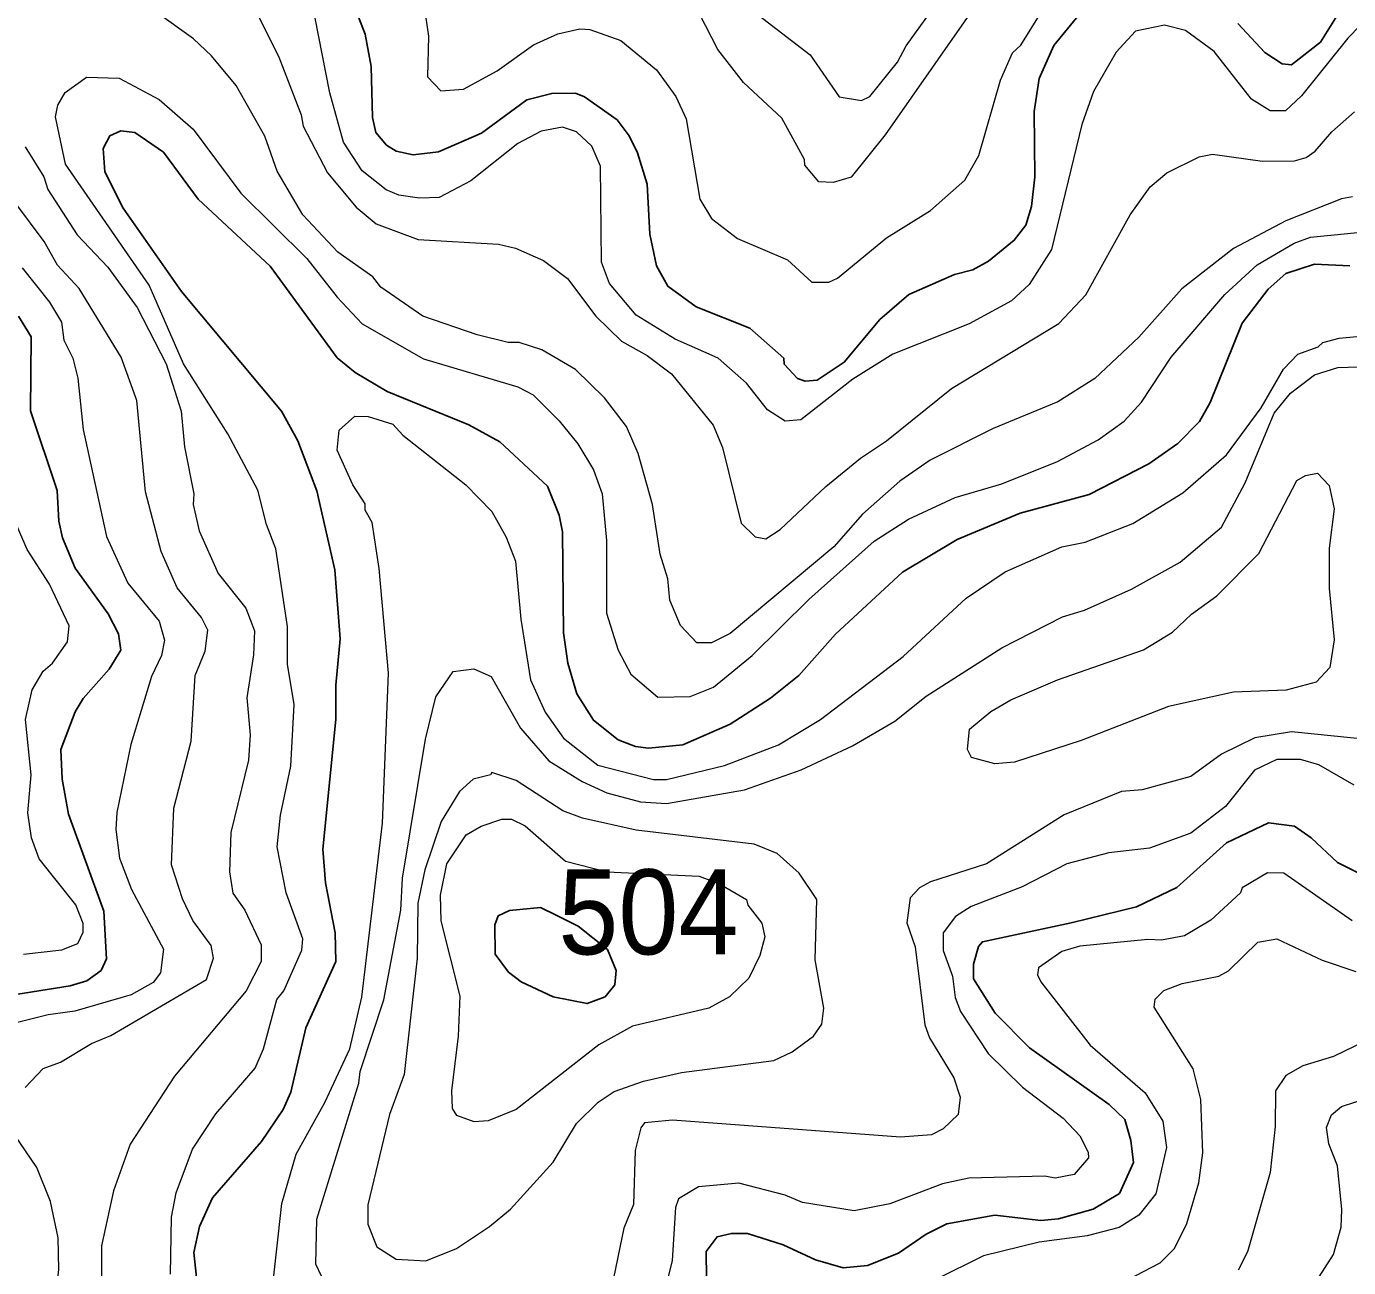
# Model space of a CAD drawing. Extents: x 673.3 to 698.5, y 6984.3 to 7012.3.
# Drawn here: x 691.793 to 693.038, y 6987.584 to 6988.753 of the extents above; entities that cross this region are included whole.
import ezdxf

# ---------------------------------------------------------------- set-up
doc = ezdxf.new("R2010")
doc.units = 0
doc.header["$LTSCALE"] = 0.032
doc.layers.add('1', color=7, linetype='Continuous', lineweight=25)
doc.layers.add('2', color=7, linetype='Continuous', lineweight=13)
doc.layers.add('21', color=7, linetype='Continuous')

msp = doc.modelspace()

# ---------------------------------------------------------------- linework, layer by layer
at = {"layer": '1'}
for points in [[(692.9334, 6988.7559), (692.9587, 6988.7284), (692.9751, 6988.7177), (692.9838, 6988.7167), (693.0111, 6988.7381), (693.0283, 6988.7658)], [(692.1053, 6988.7626), (692.112, 6988.7457), (692.1176, 6988.7153), (692.1188, 6988.6672), (692.1218, 6988.6532), (692.132, 6988.6412), (692.141, 6988.6354), (692.1572, 6988.632), (692.181, 6988.635), (692.2213, 6988.6525), (692.2641, 6988.6838), (692.2875, 6988.6899), (692.3099, 6988.69), (692.3183, 6988.6868), (692.349, 6988.6651), (692.3603, 6988.6499), (692.3683, 6988.6339), (692.3774, 6988.6043), (692.3798, 6988.5573), (692.386, 6988.5274), (692.3969, 6988.5084), (692.4236, 6988.4888), (692.4741, 6988.4687), (692.5059, 6988.4406), (692.5063, 6988.4348), (692.5189, 6988.4213), (692.5261, 6988.419), (692.5373, 6988.42), (692.5629, 6988.4368), (692.5962, 6988.477), (692.6235, 6988.5004), (692.6667, 6988.5194), (692.6839, 6988.5238), (692.6985, 6988.532), (692.7229, 6988.5516), (692.7339, 6988.5657), (692.7391, 6988.5834), (692.7422, 6988.6112), (692.7415, 6988.673), (692.7464, 6988.7039), (692.7603, 6988.7349), (692.7843, 6988.7645)], [(692.0142, 6987.7031), (692.0347, 6987.7332), (692.0419, 6987.7495), (692.056, 6987.8101), (692.0842, 6987.8725), (692.0836, 6987.8994), (692.0744, 6987.9465), (692.0721, 6987.9781), (692.0842, 6988.1003), (692.0843, 6988.1326), (692.0883, 6988.1763), (692.0834, 6988.2414), (692.0664, 6988.3157), (692.0486, 6988.3628), (692.0331, 6988.3907), (691.9389, 6988.5035), (691.8839, 6988.5819), (691.8668, 6988.616), (691.8652, 6988.6381), (691.8715, 6988.6501), (691.882, 6988.6546), (691.895, 6988.6531), (691.9219, 6988.6346), (691.9547, 6988.5904), (692.0224, 6988.5271), (692.0856, 6988.4408), (692.1023, 6988.4272), (692.1325, 6988.4091), (692.2096, 6988.3779), (692.2387, 6988.3618), (692.2835, 6988.3202), (692.2944, 6988.2929), (692.2976, 6988.2772), (692.2986, 6988.182), (692.3027, 6988.1535), (692.3112, 6988.1245), (692.3268, 6988.0996), (692.35, 6988.0813), (692.3663, 6988.0749), (692.3786, 6988.0735), (692.4109, 6988.0764), (692.4556, 6988.0961), (692.4935, 6988.1205), (692.52, 6988.1418), (692.5547, 6988.1806), (692.6177, 6988.2391), (692.6692, 6988.2698), (692.7286, 6988.2946), (692.7933, 6988.3122), (692.8495, 6988.3411), (692.8769, 6988.3604), (692.8972, 6988.381), (692.9074, 6988.3988), (692.9376, 6988.4737), (692.9619, 6988.5055), (692.9787, 6988.5202), (693.0055, 6988.5292), (693.0387, 6988.5277)], [(691.7119, 6987.83), (691.8341, 6987.8495), (691.8497, 6987.8543), (691.8635, 6987.8641), (691.8684, 6987.875), (691.866, 6987.9199), (691.8327, 6988.0112), (691.8265, 6988.0442), (691.8253, 6988.0721), (691.8388, 6988.1077), (691.8465, 6988.12), (691.871, 6988.1477), (691.8818, 6988.1655), (691.8798, 6988.1809), (691.8699, 6988.1998), (691.839, 6988.243), (691.8271, 6988.2714), (691.8236, 6988.287), (691.822, 6988.316), (691.7968, 6988.3909), (691.7975, 6988.4606), (691.7855, 6988.4803)], [(693.0717, 6987.9435), (693.0273, 6987.9658), (693.0025, 6987.989), (692.9868, 6987.9998), (692.9621, 6988.0032), (692.9228, 6987.9841), (692.876, 6987.9423), (692.8379, 6987.9239), (692.7764, 6987.9088), (692.693, 6987.8911), (692.6892, 6987.8865)], [(692.6892, 6987.8865), (692.6845, 6987.87), (692.6845, 6987.8562), (692.705, 6987.8237), (692.7371, 6987.7911), (692.8122, 6987.7378), (692.8269, 6987.7237), (692.8326, 6987.7039), (692.8351, 6987.6832), (692.822, 6987.6541), (692.7973, 6987.6392), (692.7647, 6987.6303), (692.748, 6987.6287), (692.7045, 6987.6335), (692.6593, 6987.6255), (692.6401, 6987.6158), (692.614, 6987.5979), (692.5847, 6987.5862), (692.5617, 6987.5839), (692.5358, 6987.5917), (692.5055, 6987.6056), (692.4719, 6987.6164), (692.4567, 6987.6164), (692.4431, 6987.6133), (692.4328, 6987.5994), (692.4336, 6987.5485)], [(691.9531, 6987.5749), (691.9505, 6987.5983), (691.9558, 6987.6228), (691.9683, 6987.6498), (692.0142, 6987.7031)]]:
    msp.add_lwpolyline(points, dxfattribs=at)
msp.add_lwpolyline([(692.2588, 6987.8533), (692.2468, 6987.8624), (692.2341, 6987.8795), (692.234, 6987.9069), (692.2371, 6987.9156), (692.2477, 6987.9205), (692.2769, 6987.9234), (692.2916, 6987.9162), (692.3123, 6987.9059), (692.3399, 6987.8837), (692.3482, 6987.864), (692.347, 6987.8504), (692.3377, 6987.8392), (692.3207, 6987.8328), (692.2887, 6987.8392)], close=True, dxfattribs=at)
at = {"layer": '2'}
for points in [[(692.4821, 6988.7635), (692.5307, 6988.7262), (692.5582, 6988.6866), (692.5791, 6988.6833), (692.587, 6988.6869), (692.6131, 6988.7194), (692.6212, 6988.7347), (692.6706, 6988.8038)], [(692.1633, 6988.7995), (692.1714, 6988.7437), (692.1706, 6988.7055), (692.1831, 6988.6923), (692.2045, 6988.6938), (692.236, 6988.7111), (692.2702, 6988.7356), (692.2933, 6988.7461), (692.3139, 6988.7508), (692.3233, 6988.7501), (692.3525, 6988.7397), (692.386, 6988.712), (692.4044, 6988.6871), (692.4141, 6988.6659), (692.4269, 6988.5902), (692.4379, 6988.5722), (692.4623, 6988.5533), (692.5095, 6988.5332), (692.5322, 6988.5123), (692.5482, 6988.5121), (692.5566, 6988.5158), (692.6025, 6988.5539), (692.6439, 6988.5795), (692.6764, 6988.6083), (692.6897, 6988.6314), (692.7101, 6988.7025), (692.7213, 6988.7281), (692.7292, 6988.7354), (692.7481, 6988.7662)], [(692.7004, 6988.7931), (692.6015, 6988.6509), (692.5695, 6988.611), (692.5523, 6988.606), (692.5389, 6988.6067), (692.5259, 6988.6224), (692.5254, 6988.6277), (692.504, 6988.6667), (692.468, 6988.7002), (692.4439, 6988.7313), (692.4151, 6988.7878)], [(693.0726, 6988.7791), (693.0368, 6988.7418), (692.9932, 6988.6876), (692.9783, 6988.6736), (692.9638, 6988.6736), (692.9463, 6988.6845), (692.911, 6988.7295), (692.8842, 6988.7491), (692.8642, 6988.7541), (692.837, 6988.7485), (692.8187, 6988.7286), (692.7974, 6988.6916), (692.7864, 6988.6606), (692.7579, 6988.543), (692.7369, 6988.5101), (692.7204, 6988.4945), (692.6805, 6988.4728), (692.6085, 6988.4445), (692.571, 6988.4208), (692.522, 6988.3826), (692.5071, 6988.3812), (692.4905, 6988.3919), (692.4708, 6988.4172), (692.4441, 6988.4405), (692.4037, 6988.4584), (692.3671, 6988.4812), (692.3419, 6988.5109), (692.3343, 6988.531), (692.3333, 6988.6215), (692.3252, 6988.6401), (692.3109, 6988.6538), (692.2976, 6988.658), (692.2775, 6988.6545), (692.2555, 6988.6427), (692.2113, 6988.6075), (692.1816, 6988.592), (692.163, 6988.5913), (692.1436, 6988.594), (692.1315, 6988.599), (692.1089, 6988.6171), (692.0914, 6988.644), (692.0785, 6988.6906), (692.0646, 6988.7623)], [(693.0413, 6988.5924), (693.0308, 6988.5905), (692.9784, 6988.57), (692.9293, 6988.5439), (692.8807, 6988.5058), (692.8403, 6988.4604), (692.7989, 6988.4214), (692.764, 6988.3994), (692.7029, 6988.3745), (692.6438, 6988.3445), (692.6153, 6988.3249), (692.5799, 6988.2938), (692.5531, 6988.2628), (692.4555, 6988.1813), (692.4378, 6988.1727), (692.4241, 6988.1727), (692.4088, 6988.1888), (692.3987, 6988.2128), (692.3969, 6988.2329), (692.3896, 6988.2561), (692.3822, 6988.3029), (692.3688, 6988.3508), (692.3578, 6988.3762), (692.3372, 6988.4034), (692.3098, 6988.43), (692.2783, 6988.4486), (692.2569, 6988.4552), (692.2465, 6988.4554), (692.2172, 6988.4627), (692.166, 6988.4803), (692.1266, 6988.5074), (692.119, 6988.5173), (692.0862, 6988.5403), (692.0532, 6988.5756), (692.0291, 6988.6168), (692.0175, 6988.6497), (691.9904, 6988.6973), (691.9673, 6988.7252), (691.9504, 6988.7412), (691.9138, 6988.7673)], [(692.0097, 6988.7662), (692.0303, 6988.7251), (692.0515, 6988.6697), (692.0535, 6988.6591), (692.0764, 6988.6152), (692.1033, 6988.5828), (692.1222, 6988.5671), (692.1618, 6988.5523), (692.2373, 6988.548), (692.2534, 6988.5441)], [(692.0084, 6987.7721), (692.0162, 6987.7901), (692.0287, 6987.8366), (692.0353, 6987.8447), (692.0524, 6987.883), (692.0532, 6987.8938), (692.0376, 6987.9371), (692.0289, 6987.9804), (692.0321, 6988.0104), (692.0418, 6988.0564), (692.045, 6988.1146), (692.0387, 6988.1525), (692.0386, 6988.1879), (692.0279, 6988.2611), (692.0189, 6988.284), (692.0108, 6988.3163), (691.9826, 6988.3695), (691.9407, 6988.4352), (691.9085, 6988.5095), (691.8297, 6988.6232), (691.8204, 6988.6677), (691.8227, 6988.6788), (691.8295, 6988.6908), (691.8495, 6988.7051), (691.8804, 6988.7044), (691.9179, 6988.6842), (691.95, 6988.6562), (691.9948, 6988.5959), (692.057, 6988.5345), (692.0854, 6988.4982), (692.1089, 6988.473), (692.1668, 6988.44), (692.2555, 6988.4136), (692.2699, 6988.4062), (692.2945, 6988.3817), (692.3122, 6988.3599), (692.3269, 6988.3355), (692.335, 6988.3128), (692.3391, 6988.269), (692.3391, 6988.2006), (692.35, 6988.1655), (692.3621, 6988.1431), (692.3875, 6988.1213), (692.4179, 6988.1221), (692.4399, 6988.1307), (692.4761, 6988.1606), (692.5296, 6988.2133), (692.5911, 6988.2683), (692.6233, 6988.2891), (692.6673, 6988.3094), (692.7111, 6988.3224), (692.7635, 6988.3432), (692.802, 6988.3637), (692.8263, 6988.3813)], [(692.2534, 6988.5441), (692.2797, 6988.5326), (692.3023, 6988.5157), (692.329, 6988.4802), (692.3531, 6988.4567), (692.3772, 6988.4432), (692.4002, 6988.4259), (692.4395, 6988.3774), (692.4483, 6988.3565), (692.4657, 6988.2851), (692.479, 6988.2723), (692.4891, 6988.2705), (692.5026, 6988.2792), (692.5456, 6988.3197), (692.5782, 6988.3465), (692.6025, 6988.3628), (692.6638, 6988.4119), (692.765, 6988.4731), (692.7903, 6988.5001), (692.832, 6988.5757), (692.8507, 6988.6019), (692.8666, 6988.6152), (692.897, 6988.6303), (692.9095, 6988.6327), (692.9566, 6988.626), (692.9868, 6988.6263), (692.9976, 6988.6295), (693.0063, 6988.6356), (693.022, 6988.6536), (693.0433, 6988.6726)], [(691.7917, 6988.6397), (691.8094, 6988.6114), (691.8131, 6988.5995), (691.8409, 6988.5568), (691.8697, 6988.5264), (691.8971, 6988.4884), (691.9244, 6988.4352), (691.9385, 6988.3906), (691.9419, 6988.3572), (691.9506, 6988.3127), (691.9499, 6988.3027), (691.9556, 6988.278), (691.9734, 6988.2378), (691.9996, 6988.2051), (692.0076, 6988.184), (692.0068, 6988.1613), (692.0004, 6988.1207), (692.0035, 6988.0858), (692.0019, 6988.062), (691.9854, 6987.9941), (691.984, 6987.957), (691.9874, 6987.9368), (691.9987, 6987.9209), (692.0141, 6987.8881), (692.0141, 6987.8725), (691.9999, 6987.8448), (691.9323, 6987.7644), (691.8905, 6987.7006), (691.875, 6987.6566), (691.8636, 6987.6048), (691.8636, 6987.5716)], [(691.7917, 6987.7539), (691.8087, 6987.7717), (691.825, 6987.7776), (691.8543, 6987.7954), (691.8723, 6987.8028), (691.9624, 6987.8556), (691.9692, 6987.8756), (691.9669, 6987.8876), (691.9495, 6987.911), (691.9399, 6987.9315), (691.9296, 6987.9636), (691.9317, 6988.0168), (691.9482, 6988.0798), (691.9519, 6988.1418), (691.9613, 6988.1648), (691.9636, 6988.1845), (691.9578, 6988.1963), (691.9348, 6988.2243), (691.9199, 6988.2584), (691.905, 6988.3146), (691.8969, 6988.4007), (691.8821, 6988.4417), (691.8425, 6988.5063), (691.8222, 6988.5283), (691.8098, 6988.5505), (691.7831, 6988.5862)], [(692.8263, 6988.3813), (692.8426, 6988.3993), (692.8705, 6988.4417), (692.9212, 6988.5006), (692.9517, 6988.5285), (692.9865, 6988.5488), (693.0019, 6988.5545), (693.0745, 6988.5619)], [(691.789, 6988.5258), (691.8148, 6988.4933), (691.826, 6988.4744), (691.8281, 6988.4576), (691.8366, 6988.4406), (691.8415, 6988.4218), (691.8464, 6988.3733), (691.8683, 6988.2726), (691.8885, 6988.2288), (691.9178, 6988.1931), (691.923, 6988.1752), (691.92, 6988.1605), (691.9107, 6988.141), (691.8913, 6988.0768), (691.8781, 6988.0128), (691.8773, 6987.9968), (691.8805, 6987.9697), (691.8918, 6987.9403), (691.9221, 6987.8841), (691.9193, 6987.8618), (691.9122, 6987.8526), (691.8916, 6987.841), (691.8386, 6987.8258), (691.8136, 6987.8224), (691.7543, 6987.8074)], [(692.8816, 6988.3137), (692.9226, 6988.3497), (692.9554, 6988.3939), (692.9764, 6988.4303), (692.99, 6988.4445), (693.009, 6988.4512), (693.0135, 6988.4552), (693.0288, 6988.4593), (693.0621, 6988.4626)], [(692.0709, 6987.5761), (692.0655, 6987.5875), (692.0663, 6987.6297), (692.106, 6987.7579), (692.1071, 6987.769), (692.1293, 6987.8365), (692.1453, 6987.9208), (692.1469, 6987.9509), (692.1688, 6988.0819), (692.1784, 6988.1216), (692.1946, 6988.1455), (692.2142, 6988.1482), (692.2306, 6988.1409), (692.258, 6988.0923), (692.2849, 6988.0615), (692.3161, 6988.0421), (692.3394, 6988.0312), (692.3712, 6988.0228), (692.3955, 6988.0213), (692.4691, 6988.034), (692.5223, 6988.0528), (692.5707, 6988.0754), (692.6106, 6988.0987), (692.6399, 6988.1223), (692.7113, 6988.1678), (692.7683, 6988.197), (692.7889, 6988.2033), (692.8332, 6988.223), (692.879, 6988.2485), (692.9179, 6988.2814), (692.9404, 6988.3231), (692.9675, 6988.3888), (692.9829, 6988.4077), (693.0055, 6988.4248), (693.0276, 6988.4317), (693.0471, 6988.4324)], [(692.1086, 6987.8388), (692.1281, 6988.0027), (692.1338, 6988.1439), (692.125, 6988.2425), (692.1183, 6988.2858), (692.112, 6988.2975), (692.1119, 6988.3035), (692.1004, 6988.3212), (692.0854, 6988.354), (692.0875, 6988.3729), (692.1022, 6988.386), (692.1146, 6988.3858), (692.138, 6988.3784), (692.1472, 6988.368), (692.2067, 6988.3213), (692.231, 6988.2962), (692.2446, 6988.2721), (692.2535, 6988.2495), (692.2585, 6988.1948), (692.2676, 6988.1378), (692.2814, 6988.1073), (692.2987, 6988.0827), (692.331, 6988.0572), (692.3833, 6988.044), (692.3956, 6988.044), (692.4501, 6988.0569), (692.501, 6988.0764), (692.5406, 6988.1003), (692.6184, 6988.1597), (692.6776, 6988.2146), (692.7143, 6988.2393), (692.7677, 6988.2628), (692.7898, 6988.2672), (692.8345, 6988.2848), (692.8816, 6988.3137)], [(691.7901, 6987.8794), (691.8264, 6987.8835), (691.8414, 6987.8894), (691.8464, 6987.9001), (691.8463, 6987.9081), (691.8396, 6987.9257), (691.805, 6987.9691), (691.7978, 6987.989), (691.7943, 6988.0124), (691.7975, 6988.0483), (691.792, 6988.1005), (691.7983, 6988.1284), (691.8086, 6988.146), (691.8175, 6988.1535), (691.8317, 6988.1735), (691.8333, 6988.1886), (691.8148, 6988.2278), (691.7936, 6988.2604), (691.7739, 6988.3062)], [(693.0797, 6988.0791), (692.9839, 6988.0887), (692.9494, 6988.0831), (692.9181, 6988.0676), (692.8891, 6988.0466), (692.8432, 6988.0342), (692.8237, 6988.0325), (692.7699, 6988.0106), (692.6969, 6987.9643), (692.6439, 6987.9474), (692.6337, 6987.9417), (692.625, 6987.9325), (692.6218, 6987.9089), (692.6297, 6987.8863), (692.6388, 6987.8127), (692.6432, 6987.8007), (692.666, 6987.7628), (692.6721, 6987.7446), (692.6701, 6987.7284), (692.6559, 6987.715), (692.645, 6987.7093), (692.6158, 6987.7069), (692.4013, 6987.7231), (692.3748, 6987.7204), (692.3714, 6987.7159), (692.366, 6987.6944), (692.3644, 6987.6437), (692.3553, 6987.6215), (692.3436, 6987.5652)], [(693.043, 6988.0386), (693.0096, 6988.0577), (692.9925, 6988.0628), (692.97, 6988.0628), (692.9489, 6988.0526), (692.9218, 6988.0184), (692.8891, 6987.9932), (692.8503, 6987.9793), (692.812, 6987.9747), (692.7724, 6987.9644), (692.7303, 6987.9427), (692.6823, 6987.9244), (692.6676, 6987.9147), (692.656, 6987.8994), (692.656, 6987.8828), (692.6648, 6987.8586), (692.6674, 6987.8385), (692.6723, 6987.8255), (692.6983, 6987.7857), (692.7308, 6987.754), (692.7688, 6987.7251), (692.7847, 6987.7082), (692.7925, 6987.6928), (692.7927, 6987.6875), (692.7793, 6987.6719), (692.7615, 6987.6685), (692.7516, 6987.6702), (692.6801, 6987.6685), (692.6552, 6987.6631), (692.6057, 6987.6442), (692.5722, 6987.6377), (692.5237, 6987.6454), (692.5071, 6987.6524), (692.4635, 6987.6637), (692.4257, 6987.6604), (692.4068, 6987.6489), (692.4041, 6987.6407), (692.401, 6987.591), (692.3905, 6987.5491)], [(693.0409, 6987.9107), (692.9767, 6987.9558), (692.9612, 6987.9561), (692.9373, 6987.9417), (692.9358, 6987.9372), (692.908, 6987.9114), (692.8831, 6987.8967), (692.8614, 6987.8926), (692.8486, 6987.8933), (692.7846, 6987.8868), (692.7678, 6987.8819), (692.7458, 6987.8666), (692.7447, 6987.86), (692.7478, 6987.8532), (692.7945, 6987.7938), (692.846, 6987.7488), (692.8627, 6987.722), (692.8661, 6987.6972), (692.8563, 6987.6537), (692.8401, 6987.6337), (692.8217, 6987.6221), (692.7914, 6987.614), (692.7465, 6987.6082), (692.694, 6987.5954), (692.6485, 6987.5728)], [(692.8296, 6987.5728), (692.8603, 6987.5886), (692.8737, 6987.6022), (692.8855, 6987.6257), (692.8968, 6987.664), (692.9003, 6987.6922), (692.8986, 6987.7425), (692.8914, 6987.7714), (692.8547, 6987.8294), (692.8555, 6987.8371), (692.8636, 6987.8452), (692.881, 6987.8518), (692.9155, 6987.8586), (692.9246, 6987.8637), (692.9522, 6987.8907), (692.9702, 6987.8937), (693.0126, 6987.8738), (693.0446, 6987.8632)], [(692.0232, 6987.5508), (692.0334, 6987.6445), (692.047, 6987.6911), (692.0738, 6987.7397), (692.0973, 6987.7902), (692.1086, 6987.8388)], [(693.0825, 6987.8117), (693.0234, 6987.7831), (692.9945, 6987.7743), (692.9785, 6987.7651), (692.9687, 6987.7508), (692.9686, 6987.7171), (692.9639, 6987.6737), (692.9424, 6987.5991), (692.9337, 6987.5817)], [(691.9287, 6987.5781), (691.9295, 6987.6318), (691.934, 6987.6547), (691.9492, 6987.6957), (691.9714, 6987.7291), (692.0084, 6987.7721)], [(692.9963, 6987.5545), (693.0235, 6987.5967), (693.0306, 6987.6224), (693.0313, 6987.639), (693.0273, 6987.6802), (693.019, 6987.7009), (693.0167, 6987.7163), (693.0216, 6987.728), (693.0311, 6987.7359), (693.0983, 6987.7578)], [(691.7912, 6987.3667), (691.8096, 6987.3988), (691.8342, 6987.4284), (691.8463, 6987.4542), (691.8456, 6987.46), (691.8188, 6987.5009), (691.8163, 6987.5182), (691.8236, 6987.5824), (691.8228, 6987.6124), (691.8155, 6987.6464), (691.8027, 6987.6786), (691.7814, 6987.7099)]]:
    msp.add_lwpolyline(points, dxfattribs=at)
for points in [[(692.953, 6988.2566), (692.9889, 6988.3255), (692.997, 6988.33), (693.0083, 6988.3322), (693.0192, 6988.3207), (693.024, 6988.2987), (693.0192, 6988.2616), (693.0192, 6988.2238), (693.024, 6988.1753), (693.0199, 6988.1492), (693.007, 6988.1355), (692.979, 6988.1279), (692.9293, 6988.1262), (692.8682, 6988.1125), (692.7859, 6988.0805), (692.723, 6988.0603), (692.7046, 6988.0587), (692.6827, 6988.0646), (692.6788, 6988.072), (692.6809, 6988.0912), (692.7008, 6988.108), (692.7197, 6988.119), (692.7635, 6988.1378), (692.8446, 6988.166), (692.872, 6988.1827), (692.8896, 6988.1994), (692.9135, 6988.2168)], [(692.1691, 6987.5905), (692.1977, 6987.6022), (692.229, 6987.6228), (692.2488, 6987.6394), (692.2888, 6987.6835), (692.3108, 6987.72), (692.3313, 6987.7399), (692.3462, 6987.7502), (692.3739, 6987.7597), (692.4098, 6987.7679), (692.4966, 6987.7794), (692.5139, 6987.7874), (692.5338, 6987.8023), (692.5418, 6987.8134), (692.5435, 6987.8284), (692.5354, 6987.874), (692.5371, 6987.931), (692.5203, 6987.9556), (692.4998, 6987.9742), (692.4782, 6987.983), (692.367, 6987.996), (692.3165, 6988.0075), (692.2979, 6988.0145), (692.2539, 6988.043), (692.2312, 6988.0503), (692.2298, 6988.0481), (692.2134, 6988.0441), (692.2007, 6988.0326), (692.1833, 6988.0043), (692.1681, 6987.9589), (692.1614, 6987.9273), (692.1607, 6987.8756), (692.1486, 6987.7661), (692.1348, 6987.7283), (692.1144, 6987.6433), (692.1144, 6987.6252), (692.1229, 6987.6039), (692.1409, 6987.5922)], [(692.1982, 6987.7274), (692.1942, 6987.734), (692.1933, 6987.7508), (692.1998, 6987.8023), (692.2013, 6987.8397), (692.1835, 6987.9107), (692.1828, 6987.935), (692.1886, 6987.9645), (692.2069, 6987.9919), (692.2212, 6988), (692.2406, 6988.0065), (692.2495, 6988.0065), (692.2626, 6988.0001), (692.3003, 6987.9668), (692.3397, 6987.9569), (692.4263, 6987.9527), (692.4453, 6987.9457), (692.4709, 6987.9307), (692.4722, 6987.9255), (692.4854, 6987.9086), (692.488, 6987.8956), (692.4835, 6987.878), (692.4731, 6987.8569), (692.4547, 6987.8391), (692.4355, 6987.8286), (692.3636, 6987.8117), (692.3318, 6987.7939), (692.2539, 6987.733), (692.2275, 6987.7223), (692.2145, 6987.7215)]]:
    msp.add_lwpolyline(points, close=True, dxfattribs=at)

# ---------------------------------------------------------------- texts
at = {"layer": '21', "width": 0.95}
msp.add_text('504', height=0.08, dxfattribs=at).set_placement((692.2937, 6987.8792))

doc.saveas('drawing.dxf')
